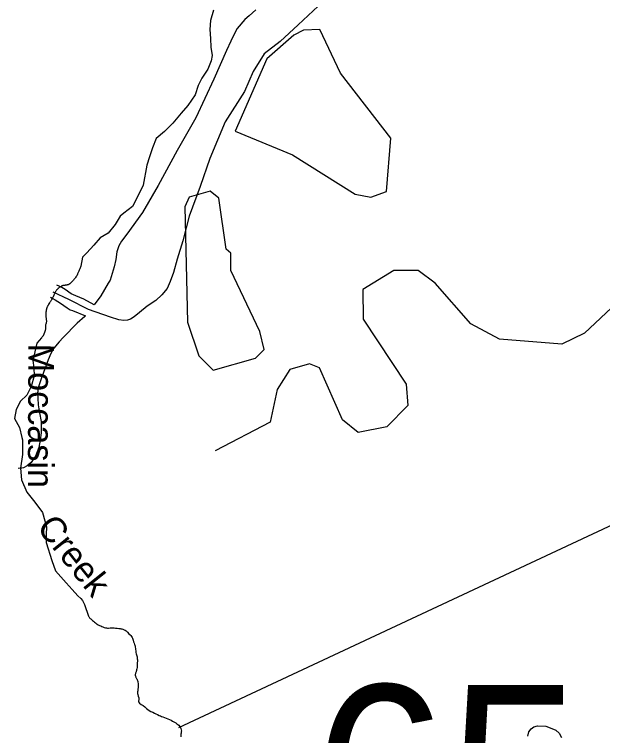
# Model space of a CAD drawing. Extents: x 2206922 to 2357709, y 510027 to 673830.
# Drawn here: x 2249689 to 2253143, y 587773 to 592005 of the extents above; entities that cross this region are included whole.
import ezdxf

# ---------------------------------------------------------------- set-up
doc = ezdxf.new("R2010")
doc.units = 0
for name, color, linetype in [('Exist Boundary Political CountyLine', 7, 'Continuous'), ('Exist Hydrographic Creek Single Shore', 7, 'Continuous'), ('Exist Hydrographic Creek Single Shore Label', 7, 'Continuous'), ('Exist Hydrographic Misc Water Feature', 7, 'Continuous'), ('Exist Hydrographic Pond Under 1500 Sq Ft', 7, 'Continuous'), ('Exist Road Non-System Type 51', 7, 'Continuous'), ('Exist Road Secondary Structure Standard Bridge Number Label', 7, 'Continuous'), ('Exist Utilities Electrical Transmission Line', 7, 'Continuous')]:
    doc.layers.add(name, color=color, linetype=linetype)

msp = doc.modelspace()

# ---------------------------------------------------------------- linework, layer by layer
at = {"layer": 'Exist Boundary Political CountyLine'}
for points in [[(2250858.6, 592030.1), (2250840.3, 591969.7), (2250837, 591916.4), (2250840.5, 591863.9), (2250842.8, 591813.4), (2250850.2, 591763.7), (2250844.4, 591732.4), (2250825.6, 591683.6), (2250789.7, 591630.7), (2250767.3, 591587.1), (2250750.7, 591532.3), (2250707.9, 591469.5), (2250668.7, 591424.7), (2250618.4, 591366.3), (2250571.1, 591317.1), (2250522.1, 591276.8), (2250500.3, 591221.9), (2250481.1, 591168.2), (2250466.3, 591120.6), (2250444.6, 591003.3)], [(2250444.6, 591003.3), (2250416.3, 590942), (2250382, 590878.4), (2250330.4, 590837.6), (2250310, 590820.4), (2250280.3, 590772.8), (2250239.7, 590721.6), (2250193.2, 590693.2), (2250155, 590650.5), (2250113.8, 590606.1), (2250088, 590580.9), (2250078.3, 590526.7), (2250076.9, 590521.6), (2250074.7, 590517.1), (2250072.8, 590512.5), (2250070.5, 590507.8), (2250068.5, 590503.1), (2250066.7, 590498.5), (2250064.8, 590494.1), (2250063, 590489.8), (2250061.3, 590485.8), (2250059.7, 590482.2), (2250058.5, 590478.9), (2250057.4, 590476.7), (2250056.2, 590474.3), (2250054.8, 590471.8), (2250052.9, 590469.2), (2250051.3, 590466.5), (2250047.2, 590460.9), (2250044.9, 590458), (2250040.4, 590452.1), (2250037.9, 590449.2), (2250035.7, 590446.2), (2250033.2, 590443.4), (2250031.6, 590441.2), (2250029.5, 590439.1), (2250027.7, 590436.9), (2250026.1, 590434.9), (2250024.2, 590432.9), (2250022.2, 590431), (2250020.5, 590429.2), (2250018.5, 590427.4), (2250016.8, 590425.8), (2250014.8, 590424.3), (2250012.9, 590422.9), (2250011.1, 590421.7), (2250009, 590420.6), (2250006.8, 590419.5), (2250004.3, 590418.6), (2250001.4, 590417.8), (2249998.8, 590417.1), (2249995.7, 590416.5), (2249992.8, 590416), (2249986.7, 590415.1), (2249983.8, 590414.8), (2249980.7, 590414.5), (2249978.1, 590414.1), (2249975.4, 590413.7), (2249973.1, 590413.4), (2249970.7, 590412.8), (2249968, 590411.8), (2249965.2, 590410.6), (2249962.5, 590409.1), (2249958, 590406.4), (2249955.3, 590404.6), (2249953.5, 590403.4), (2249952, 590402.2), (2249950.2, 590400.9), (2249945.7, 590397.2), (2249944.2, 590395.9), (2249943, 590394.6), (2249941.6, 590393.3), (2249938.9, 590390.7), (2249936.7, 590388.1), (2249935, 590386), (2249933.2, 590383.5), (2249931.5, 590380.8), (2249930.1, 590378), (2249928.4, 590375), (2249926.8, 590372), (2249925.6, 590368.9), (2249923.9, 590366), (2249922.7, 590363), (2249921.5, 590360.3), (2249920.5, 590357.8), (2249919.4, 590355.5), (2249918.8, 590353.4), (2249918, 590351.3), (2249916.8, 590349), (2249915.5, 590346.6), (2249914.3, 590344.1), (2249912.7, 590341.5), (2249909.2, 590335.8), (2249907.5, 590332.8), (2249905.7, 590329.9), (2249903.8, 590326.9), (2249901.8, 590323.8), (2249899.9, 590320.8), (2249898.1, 590317.7), (2249896.3, 590315), (2249894.4, 590312.2)], [(2249894.4, 590312.2), (2249890.9, 590306.8), (2249889.5, 590304.1), (2249888.1, 590301.5), (2249885, 590296.4), (2249882.5, 590291.4), (2249881.3, 590288.9), (2249880.3, 590286.5), (2249879.2, 590284.1), (2249878.4, 590281.8), (2249877.8, 590279.3), (2249877, 590276.7), (2249876.2, 590273.9), (2249875.7, 590270.9), (2249875.3, 590268), (2249874.3, 590262.1), (2249873.9, 590259.2), (2249873.5, 590256.5), (2249873.3, 590254), (2249873.1, 590251.5), (2249872.7, 590249.3), (2249872.5, 590240.4), (2249873.1, 590236.3), (2249873.1, 590234.2), (2249873.3, 590232), (2249873.7, 590227.5), (2249874.3, 590225.2), (2249874.5, 590222.9), (2249875.3, 590217.7), (2249875.7, 590214.3), (2249876, 590212.7), (2249876.6, 590209.6), (2249876.8, 590206.7), (2249876.8, 590202.9), (2249876.2, 590200.2), (2249875.5, 590197), (2249874.5, 590193.5), (2249872.5, 590186.2), (2249871.4, 590182.9), (2249871, 590179.4), (2249870.8, 590177.4), (2249870.8, 590162.5), (2249870.4, 590160.1), (2249870.4, 590157.8), (2249870.2, 590155.4), (2249869.8, 590152.9), (2249868.8, 590148.4), (2249868, 590146.1), (2249867.5, 590143.9), (2249866.7, 590141.7), (2249865.9, 590139.5), (2249865.3, 590137.5), (2249864.5, 590135.6), (2249864.1, 590133.8), (2249863.2, 590132.2), (2249862.2, 590129.5), (2249861.6, 590127.4), (2249860.2, 590124.7), (2249859.3, 590123.1), (2249857.9, 590121.4), (2249856.7, 590119.5), (2249855.2, 590117.7), (2249853.8, 590115.7), (2249852.2, 590113.5), (2249848.7, 590109.3), (2249847, 590107.1), (2249820.8, 590076.2), (2249795.8, 589974.4), (2249801.7, 589931.6), (2249804.6, 589884.5), (2249787.8, 589821.6), (2249761.7, 589770.8), (2249724.8, 589736), (2249698.6, 589686.8), (2249688.5, 589632.8), (2249717.7, 589580), (2249732.4, 589522.6), (2249735.9, 589508.4), (2249736.7, 589422.8), (2249725.2, 589341.6), (2249730.8, 589273.6), (2249761.7, 589200.4), (2249799.7, 589152.4), (2249819.6, 589126.4), (2249853.2, 589082.1), (2249876.6, 588997.2), (2249874.7, 588953.6), (2249874.7, 588906.5), (2249907.9, 588800.8), (2249930.1, 588740.4), (2249991.8, 588670.1), (2250027.3, 588630.8), (2250060.7, 588593.6), (2250078.3, 588577.3), (2250088, 588565), (2250100.5, 588542.6), (2250124.3, 588474), (2250125.3, 588471.4), (2250127.6, 588467.4), (2250129.8, 588464.1)], [(2250129.8, 588464.1), (2250131.4, 588461.7), (2250133.7, 588459.6), (2250137, 588456.9), (2250140.7, 588454.1), (2250147.2, 588449), (2250153, 588444.2), (2250159.3, 588438.9), (2250165.3, 588434), (2250171, 588429.5), (2250175.3, 588426.1), (2250180.5, 588423), (2250187.8, 588419.6), (2250195.4, 588416.1), (2250202.2, 588413), (2250208.8, 588410.2), (2250215.9, 588407.8), (2250222.9, 588405.9), (2250229.7, 588404.5), (2250234.8, 588403.8), (2250241.8, 588403.9), (2250251, 588404.7), (2250260.4, 588405.4), (2250268, 588405.1), (2250275, 588404.3), (2250282.6, 588403.4), (2250292.4, 588402.4), (2250302.3, 588401.6), (2250310, 588401), (2250314.2, 588400.1), (2250319.7, 588398.7), (2250325.2, 588397), (2250332.8, 588394.2), (2250339.2, 588391), (2250345.5, 588387), (2250353.7, 588379.2), (2250361.3, 588370.7), (2250368.1, 588363.7), (2250372.2, 588359.8), (2250376.7, 588354.9), (2250380.6, 588349.3), (2250383, 588343.8), (2250384.5, 588338.1), (2250385.9, 588332.1), (2250389, 588322.9), (2250392.1, 588314.2), (2250394.7, 588306.9), (2250396, 588302.6), (2250397, 588297.2), (2250398, 588291.8), (2250399, 588284.3), (2250400.1, 588277.1), (2250401.3, 588269.3), (2250402.7, 588260.7), (2250404, 588252.9), (2250405.4, 588247), (2250407, 588241.6), (2250408.7, 588234.6), (2250409.9, 588227.3), (2250410.5, 588222.6), (2250410.7, 588218), (2250410.7, 588206.5), (2250410.5, 588200.7), (2250410.5, 588191.4), (2250410.3, 588185.2), (2250409.9, 588178.9), (2250409.5, 588171.9), (2250408.5, 588165.2), (2250406.4, 588157.8), (2250405.4, 588154.8), (2250404.8, 588152.2), (2250404, 588150.1), (2250403.3, 588147), (2250401.9, 588143.3), (2250400.7, 588139.3), (2250399.2, 588135.3), (2250398.2, 588131.2), (2250398.4, 588126.5), (2250399.7, 588121.7), (2250401.3, 588117.6), (2250402.7, 588114.5), (2250404.2, 588111.8), (2250406, 588108.5), (2250408.1, 588105), (2250412.6, 588090.6), (2250415.4, 588074.6), (2250415.2, 588055.7), (2250414.8, 588051.2), (2250414, 588047.3), (2250413.6, 588044.9), (2250413, 588041.5), (2250412.6, 588036.2), (2250412, 588030.1), (2250411.8, 588024.3), (2250412, 588019), (2250412.8, 588014.1), (2250415.4, 588004.1), (2250418.5, 587993.7), (2250419.3, 587984.5), (2250418.7, 587980.6)], [(2250418.7, 587980.6), (2250417.9, 587976.2), (2250417.9, 587971.7), (2250422.8, 587962.3), (2250432.7, 587955.4), (2250444.6, 587948.9), (2250455.4, 587940.7), (2250465.1, 587932.1), (2250472, 587925.3), (2250479.8, 587920.3), (2250490.7, 587915), (2250502, 587909.7), (2250511, 587905.1), (2250519.4, 587900.4), (2250528.8, 587895.7), (2250538.1, 587891.4), (2250547.1, 587887.8), (2250553.2, 587885.3), (2250560.2, 587882.8), (2250570.1, 587879.2), (2250580.5, 587875.3), (2250590.2, 587871.3), (2250599.2, 587867.2), (2250608.4, 587862.5), (2250617.2, 587858.1), (2250625.4, 587853.8), (2250632, 587850.1), (2250636.9, 587846.9), (2250642.8, 587842.4), (2250648.8, 587837.7), (2250653.9, 587833.3), (2250658.8, 587828.8), (2250662.7, 587823.3), (2250666.4, 587814.9), (2250668.5, 587806), (2250669.3, 587798.9), (2250668.5, 587793.9), (2250667.3, 587787.6), (2250666, 587780.9), (2250665.4, 587772.9), (2250666.8, 587765.2)]]:
    msp.add_lwpolyline(points, dxfattribs=at)
at = {"layer": 'Exist Hydrographic Creek Single Shore'}
msp.add_lwpolyline([(2253227.3, 590311.9), (2253036.2, 590135.3), (2252904.4, 590069.2), (2252537.3, 590099.6), (2252370.2, 590188.2), (2252160.2, 590428.6), (2252059.3, 590502.8), (2251917.2, 590502.3), (2251735.4, 590391.3), (2251736.4, 590217.4), (2251989.2, 589835.1), (2251999.3, 589710.4), (2251875.2, 589584.9), (2251708.3, 589552.2), (2251616.2, 589626.2), (2251480.3, 589930.7), (2251422.3, 589954.8), (2251306.2, 589921.2), (2251232.4, 589804.5), (2251191.4, 589611.8), (2250868.2, 589444.6)], dxfattribs=at)
at = {"layer": 'Exist Hydrographic Misc Water Feature'}
for p, q in [((2249952, 590409.5), (2249937.5, 590416.6)), ((2249900.3, 590345.9), (2249911, 590339.1)), ((2249725, 589341.9), (2249710.2, 589339.6))]:
    msp.add_line(p, q, dxfattribs=at)
for points in [[(2251106.7, 592032), (2251067.1, 591995.8), (2251041.1, 591975.3), (2250997.6, 591923.1), (2250983.9, 591896.8), (2250960.1, 591848.9), (2250934.6, 591792.7), (2250860.2, 591625.9), (2250754, 591397.3), (2250645.3, 591206.5), (2250533.6, 591001.9), (2250440.5, 590843.2), (2250348, 590714.5), (2250317.8, 590674.4), (2250302.3, 590646.3), (2250290.6, 590612), (2250285, 590566.1), (2250275, 590523.9), (2250263.7, 590483.8), (2250250.2, 590445.7), (2250239.9, 590427.8), (2250196.9, 590353.6), (2250157.1, 590301.2), (2250096.8, 590334.6), (2250048.6, 590354), (2250022.6, 590366.1), (2249986.7, 590389.8), (2249966.6, 590401.7), (2249952, 590409.5)], [(2249911, 590339.1), (2249928.9, 590329.1), (2249959.2, 590309.5), (2249999.2, 590283.6), (2250015.4, 590271.8), (2250029.7, 590268.1), (2250105.6, 590236.7), (2250101.5, 590232.5), (2250057.8, 590192.4), (2249974.8, 590109.7), (2249951, 590083.7), (2249919.4, 590047.1), (2249903.4, 590015), (2249886, 589977.1), (2249844.8, 589866.9), (2249827.2, 589812.8), (2249823.5, 589780.5), (2249825.7, 589752.6), (2249827.8, 589714.6), (2249836.4, 589666.6), (2249844.8, 589615.1), (2249845.4, 589548.9), (2249840.1, 589506.7), (2249832.3, 589462.9), (2249812.4, 589412.7), (2249787, 589374.4), (2249763.2, 589356.5), (2249741, 589344), (2249733, 589341.9), (2249725, 589341.9)], [(2252704.4, 587769), (2252710, 587794.9), (2252724.1, 587813.1), (2252739.9, 587823.3), (2252761.7, 587829.3), (2252809.8, 587827.7), (2252835.9, 587818.1), (2252868.1, 587804.4), (2252888, 587786.7), (2252902.3, 587760.6)]]:
    msp.add_lwpolyline(points, dxfattribs=at)
at = {"layer": 'Exist Hydrographic Pond Under 1500 Sq Ft'}
for points in [[(2251782.7, 590932.3), (2251873.7, 590966.5), (2251900, 591278.6), (2251603.9, 591660.9), (2251482.7, 591915.7), (2251387.4, 591912.5), (2251330.1, 591883.9), (2251170.9, 591743.7), (2250986.2, 591320), (2251322.7, 591181), (2251690.8, 590950.5), (2251782.7, 590932.3)], [(2250856.3, 589917.1), (2251105.2, 589987.5), (2251155.3, 590039), (2251129.2, 590144.5), (2250959.2, 590502.1), (2250959.2, 590603.8), (2250933.2, 590627.2), (2250889.3, 590926.6), (2250839.3, 590967), (2250714.2, 590933.4), (2250690.2, 590874.9), (2250704.4, 590199), (2250772.2, 590000.8), (2250856.3, 589917.1)]]:
    msp.add_lwpolyline(points, dxfattribs=at)
at = {"layer": 'Exist Road Non-System Type 51'}
msp.add_lwpolyline([(2251473.4, 592052.7), (2251355.6, 591944.4), (2251250.5, 591845.6), (2251155.2, 591773), (2251091.3, 591670.4), (2251040.4, 591552.6), (2250925.6, 591374.4), (2250836.6, 591158.8), (2250780.4, 590994.7), (2250714.8, 590821.2), (2250677.3, 590675.9), (2250644.5, 590568), (2250623.1, 590489.9), (2250604.4, 590437.8), (2250585.6, 590396.1), (2250554.4, 590358.6), (2250519, 590325.3), (2250469, 590291.9), (2250423.2, 590256.5), (2250392, 590229.4), (2250371.1, 590216.9), (2250352.4, 590210.7), (2250331.6, 590208.6), (2250302.4, 590212.7), (2250252.4, 590227.3), (2250123.3, 590273.2), (2250008.8, 590331.5), (2249917.1, 590375.7)], dxfattribs=at)
at = {"layer": 'Exist Utilities Electrical Transmission Line'}
msp.add_lwpolyline([(2259140.2, 591693.5), (2258177.2, 591318.5), (2254725.7, 589721.2), (2250652.4, 587817.9)], dxfattribs=at)

# ---------------------------------------------------------------- texts
at = {"layer": 'Exist Hydrographic Creek Single Shore Label'}
for s, rotation, p in [('Moccasin', 269.7975, (2249770.7, 590073)), ('Creek', 308.6247, (2249813.7, 588993.1))]:
    msp.add_text(s, height=150, rotation=rotation, dxfattribs=at).set_placement(p)
at = {"layer": 'Exist Road Secondary Structure Standard Bridge Number Label'}
msp.add_text('65', height=1066.27, dxfattribs=at).set_placement((2251441.9, 587002.7))

doc.saveas('drawing.dxf')
